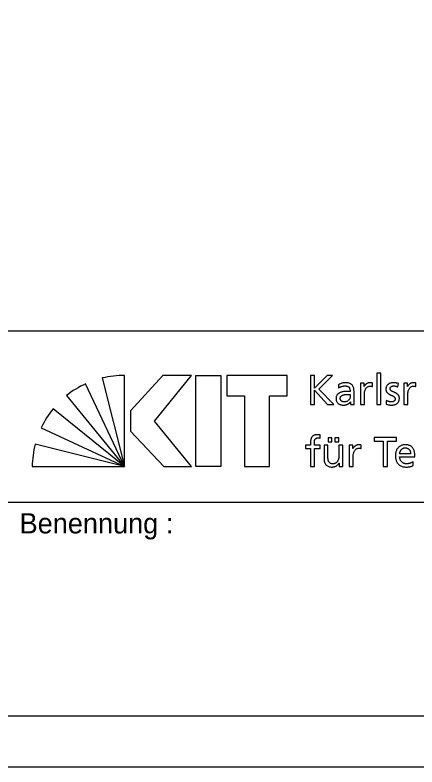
# Model space of a CAD drawing. Extents: x 0 to 42, y 0 to 59.4.
# Drawn here: x 24.33 to 32.27, y 0 to 14.85 of the extents above; entities that cross this region are included whole.
import ezdxf

# ---------------------------------------------------------------- set-up
doc = ezdxf.new("R2010")
doc.units = 0
doc.layers.add('90_Plankopf', color=7, linetype='Continuous')

msp = doc.modelspace()

# ---------------------------------------------------------------- linework, layer by layer
at = {"layer": '90_Plankopf'}
for p, q in [((5, 8.614), (41, 8.614)), ((26.496, 5.933), (26.496, 7.733)), ((30.162, 7.733), (30.162, 7.157)), ((26.055, 7.683), (26.496, 5.933)), ((31.385, 7.513), (31.385, 7.582)), ((32.242, 7.513), (32.242, 7.582)), ((26.496, 5.933), (25.727, 7.566)), ((30.716, 7.548), (30.72, 7.482)), ((31.891, 7.504), (31.898, 7.572)), ((25.349, 7.333), (26.496, 5.933)), ((30.946, 7.358), (30.946, 7.321)), ((31.024, 7.24), (31.024, 7.414)), ((30.162, 7.157), (30.244, 7.157)), ((30.501, 7.157), (30.622, 7.157)), ((31.659, 7.24), (31.655, 7.17)), ((26.496, 5.933), (25.087, 7.073)), ((24.848, 6.699), (26.496, 5.933)), ((30.355, 6.495), (30.358, 6.557)), ((26.496, 5.933), (24.732, 6.374)), ((31.165, 6.289), (31.165, 6.358)), ((32.141, 6.184), (31.923, 6.184)), ((31.923, 6.126), (32.224, 6.126)), ((32.192, 5.951), (32.192, 6.028)), ((24.673, 5.933), (26.496, 5.933)), ((21.73, 5.23), (41, 5.23))]:
    msp.add_line(p, q, dxfattribs=at)
for points in [[(0, 0), (42, 0), (42, 59.4), (0, 59.4)], [(5, 58.4), (41, 58.4), (41, 1), (5, 1)], [(27.813, 7.733), (27.247, 7.733), (26.615, 7.036), (26.615, 6.634), (27.268, 5.933), (27.817, 5.933), (27.084, 6.829)], [(28.394, 7.733), (28.394, 5.933), (27.9, 5.933), (27.9, 7.733)], [(28.512, 7.733), (28.512, 7.328), (28.86, 7.328), (28.86, 5.933), (29.354, 5.933), (29.354, 7.328), (29.702, 7.328), (29.702, 7.733)]]:
    msp.add_lwpolyline(points, close=True, dxfattribs=at)
for points in [[(30.622, 7.157), (30.329, 7.461), (30.6, 7.733), (30.49, 7.733), (30.244, 7.48), (30.244, 7.733), (30.162, 7.733)], [(31.476, 7.157), (31.554, 7.157), (31.554, 7.776), (31.476, 7.776), (31.476, 7.157)], [(31.224, 7.513), (31.223, 7.513), (31.223, 7.578), (31.15, 7.578), (31.15, 7.157), (31.228, 7.157), (31.228, 7.349)], [(32.081, 7.513), (32.08, 7.513), (32.08, 7.578), (32.007, 7.578), (32.007, 7.157), (32.085, 7.157), (32.085, 7.349)], [(30.244, 7.157), (30.244, 7.439), (30.501, 7.157)], [(30.953, 7.212), (30.954, 7.212), (30.954, 7.157), (31.027, 7.157)], [(30.165, 6.393), (30.165, 6.354), (30.066, 6.354), (30.066, 6.292), (30.165, 6.292), (30.165, 5.933), (30.242, 5.933), (30.242, 6.292), (30.354, 6.292), (30.354, 6.354), (30.242, 6.354), (30.242, 6.4)], [(30.511, 6.501), (30.511, 6.419), (30.588, 6.419), (30.588, 6.501), (30.511, 6.501)], [(30.646, 6.501), (30.646, 6.419), (30.724, 6.419), (30.724, 6.501), (30.646, 6.501)], [(31.598, 5.933), (31.681, 5.933), (31.681, 6.437), (31.86, 6.437), (31.86, 6.509), (31.419, 6.509), (31.419, 6.437), (31.598, 6.437), (31.598, 5.933)], [(30.508, 6.136), (30.508, 6.354), (30.431, 6.354), (30.431, 6.104)], [(30.803, 5.933), (30.803, 6.354), (30.725, 6.354), (30.725, 6.159)], [(31.004, 6.289), (31.003, 6.289), (31.003, 6.354), (30.93, 6.354), (30.93, 5.933), (31.008, 5.933), (31.008, 6.125)], [(30.726, 6), (30.728, 6), (30.728, 5.933), (30.803, 5.933)]]:
    msp.add_lwpolyline(points, dxfattribs=at)
for centre, start, end in [((26.49, 5.827), 89.8053, 103.1895), ((26.532, 5.84), 115.0126, 128.3968), ((26.563, 5.869), 140.7898, 154.174), ((26.578, 5.904), 165.7222, 179.1064)]:
    msp.add_arc(centre, 1.906, start, end, dxfattribs=at)
for points in [[(31.024, 7.414), (31.024, 7.452), (31.018, 7.484), (31.007, 7.51), (30.995, 7.536), (30.977, 7.555), (30.952, 7.568), (30.927, 7.581), (30.894, 7.588), (30.854, 7.588), (30.828, 7.588), (30.803, 7.584), (30.78, 7.577), (30.756, 7.57), (30.735, 7.56), (30.716, 7.548)], [(31.385, 7.582), (31.38, 7.583), (31.375, 7.584), (31.37, 7.585), (31.365, 7.586), (31.36, 7.587), (31.354, 7.587), (31.348, 7.588), (31.342, 7.588), (31.334, 7.588), (31.319, 7.588), (31.305, 7.585), (31.29, 7.578), (31.276, 7.572), (31.264, 7.563), (31.252, 7.552), (31.241, 7.541), (31.231, 7.528), (31.224, 7.513)], [(31.898, 7.572), (31.883, 7.576), (31.867, 7.58), (31.852, 7.583), (31.836, 7.586), (31.819, 7.588), (31.801, 7.588), (31.781, 7.588), (31.761, 7.585), (31.743, 7.58), (31.725, 7.575), (31.709, 7.567), (31.696, 7.556), (31.682, 7.545), (31.672, 7.532), (31.664, 7.516), (31.657, 7.499), (31.653, 7.48), (31.653, 7.458), (31.653, 7.442), (31.656, 7.427), (31.663, 7.415), (31.669, 7.403), (31.678, 7.392), (31.689, 7.383), (31.7, 7.374), (31.712, 7.366), (31.725, 7.359), (31.738, 7.352), (31.751, 7.345), (31.763, 7.339), (31.776, 7.333), (31.788, 7.327), (31.799, 7.32), (31.81, 7.314), (31.819, 7.307), (31.825, 7.299), (31.832, 7.291), (31.835, 7.281), (31.835, 7.27), (31.835, 7.259), (31.833, 7.249), (31.828, 7.242), (31.823, 7.234), (31.817, 7.228), (31.809, 7.223), (31.801, 7.218), (31.793, 7.215), (31.783, 7.213), (31.774, 7.211), (31.765, 7.21), (31.756, 7.21), (31.748, 7.21), (31.739, 7.211), (31.728, 7.213), (31.717, 7.215), (31.705, 7.219), (31.693, 7.223), (31.681, 7.228), (31.67, 7.233), (31.659, 7.24)], [(32.242, 7.582), (32.237, 7.583), (32.232, 7.584), (32.227, 7.585), (32.222, 7.586), (32.217, 7.587), (32.211, 7.587), (32.205, 7.588), (32.199, 7.588), (32.191, 7.588), (32.176, 7.588), (32.162, 7.585), (32.147, 7.578), (32.133, 7.572), (32.121, 7.563), (32.109, 7.552), (32.098, 7.541), (32.088, 7.528), (32.081, 7.513)], [(30.72, 7.482), (30.731, 7.491), (30.743, 7.499), (30.756, 7.505), (30.769, 7.512), (30.783, 7.517), (30.798, 7.52), (30.813, 7.524), (30.827, 7.525), (30.842, 7.525), (30.868, 7.525), (30.888, 7.521), (30.904, 7.513), (30.919, 7.505), (30.93, 7.493), (30.936, 7.476), (30.943, 7.46), (30.946, 7.44), (30.946, 7.415)], [(31.228, 7.349), (31.228, 7.384), (31.233, 7.415), (31.242, 7.44), (31.251, 7.466), (31.265, 7.486), (31.282, 7.499), (31.299, 7.513), (31.319, 7.52), (31.342, 7.52), (31.349, 7.52), (31.356, 7.52), (31.364, 7.519), (31.371, 7.518), (31.378, 7.516), (31.385, 7.513)], [(31.655, 7.17), (31.673, 7.161), (31.692, 7.155), (31.712, 7.152), (31.731, 7.148), (31.751, 7.147), (31.771, 7.147), (31.79, 7.147), (31.808, 7.15), (31.825, 7.155), (31.843, 7.16), (31.859, 7.168), (31.873, 7.179), (31.886, 7.19), (31.897, 7.204), (31.905, 7.22), (31.914, 7.237), (31.918, 7.256), (31.918, 7.278), (31.918, 7.298), (31.914, 7.314), (31.908, 7.327), (31.901, 7.34), (31.892, 7.352), (31.882, 7.361), (31.871, 7.37), (31.859, 7.378), (31.846, 7.385), (31.833, 7.392), (31.82, 7.398), (31.807, 7.403), (31.794, 7.409), (31.782, 7.415), (31.772, 7.421), (31.761, 7.428), (31.752, 7.435), (31.745, 7.443), (31.739, 7.452), (31.736, 7.462), (31.735, 7.474), (31.736, 7.486), (31.739, 7.495), (31.746, 7.503), (31.753, 7.51), (31.762, 7.516), (31.773, 7.52), (31.784, 7.524), (31.796, 7.525), (31.81, 7.525), (31.814, 7.525), (31.82, 7.525), (31.828, 7.524), (31.835, 7.522), (31.843, 7.521), (31.851, 7.519), (31.859, 7.517), (31.867, 7.514), (31.874, 7.512), (31.881, 7.509), (31.887, 7.507), (31.891, 7.504)], [(32.085, 7.349), (32.085, 7.384), (32.09, 7.415), (32.099, 7.44), (32.108, 7.466), (32.122, 7.486), (32.139, 7.499), (32.156, 7.513), (32.176, 7.52), (32.199, 7.52), (32.206, 7.52), (32.213, 7.52), (32.221, 7.519), (32.228, 7.518), (32.235, 7.516), (32.242, 7.513)], [(30.946, 7.415), (30.936, 7.416), (30.927, 7.416), (30.918, 7.417), (30.909, 7.417), (30.9, 7.417), (30.892, 7.417), (30.883, 7.417), (30.874, 7.417), (30.864, 7.417), (30.847, 7.417), (30.83, 7.416), (30.813, 7.413), (30.795, 7.41), (30.777, 7.405), (30.76, 7.399), (30.743, 7.392), (30.728, 7.384), (30.714, 7.373), (30.7, 7.362), (30.689, 7.349), (30.681, 7.334), (30.672, 7.318), (30.668, 7.3), (30.668, 7.278), (30.668, 7.248), (30.675, 7.223), (30.688, 7.204), (30.701, 7.184), (30.719, 7.17), (30.742, 7.161), (30.765, 7.152), (30.792, 7.147), (30.822, 7.147), (30.84, 7.147), (30.856, 7.15), (30.87, 7.154), (30.884, 7.158), (30.897, 7.163), (30.907, 7.17), (30.918, 7.176), (30.927, 7.183), (30.935, 7.191), (30.942, 7.198), (30.948, 7.205), (30.953, 7.212)], [(30.946, 7.321), (30.946, 7.3), (30.942, 7.281), (30.933, 7.264), (30.924, 7.247), (30.911, 7.234), (30.893, 7.225), (30.876, 7.215), (30.854, 7.21), (30.829, 7.21), (30.82, 7.21), (30.811, 7.212), (30.802, 7.214), (30.793, 7.217), (30.784, 7.222), (30.776, 7.227), (30.769, 7.233), (30.762, 7.241), (30.758, 7.249), (30.753, 7.257), (30.751, 7.267), (30.75, 7.278), (30.751, 7.293), (30.754, 7.306), (30.762, 7.315), (30.769, 7.325), (30.778, 7.333), (30.79, 7.339), (30.801, 7.345), (30.814, 7.349), (30.827, 7.352), (30.84, 7.355), (30.853, 7.357), (30.865, 7.358), (30.877, 7.359), (30.888, 7.359), (30.897, 7.359), (30.905, 7.359), (30.913, 7.359), (30.921, 7.359), (30.93, 7.358), (30.938, 7.358), (30.946, 7.358)], [(31.027, 7.157), (31.026, 7.161), (31.026, 7.167), (31.025, 7.173), (31.025, 7.18), (31.024, 7.189), (31.024, 7.2), (31.024, 7.211), (31.024, 7.224), (31.024, 7.24)], [(30.358, 6.557), (30.35, 6.558), (30.342, 6.56), (30.334, 6.561), (30.325, 6.562), (30.316, 6.562), (30.306, 6.562), (30.278, 6.562), (30.254, 6.558), (30.236, 6.55), (30.217, 6.542), (30.203, 6.531), (30.192, 6.516), (30.182, 6.501), (30.175, 6.483), (30.171, 6.463), (30.167, 6.442), (30.165, 6.419), (30.165, 6.393)], [(30.242, 6.4), (30.242, 6.414), (30.243, 6.427), (30.245, 6.439), (30.246, 6.451), (30.25, 6.462), (30.255, 6.471), (30.26, 6.48), (30.268, 6.487), (30.278, 6.492), (30.288, 6.497), (30.301, 6.499), (30.318, 6.499), (30.324, 6.499), (30.331, 6.499), (30.338, 6.498), (30.344, 6.497), (30.35, 6.496), (30.355, 6.495)], [(31.165, 6.358), (31.16, 6.359), (31.155, 6.36), (31.15, 6.361), (31.145, 6.362), (31.14, 6.363), (31.134, 6.363), (31.128, 6.364), (31.122, 6.364), (31.114, 6.364), (31.099, 6.364), (31.085, 6.361), (31.07, 6.354), (31.056, 6.348), (31.044, 6.339), (31.032, 6.328), (31.021, 6.317), (31.011, 6.304), (31.004, 6.289)], [(31.008, 6.125), (31.008, 6.16), (31.013, 6.191), (31.022, 6.216), (31.032, 6.242), (31.045, 6.262), (31.062, 6.275), (31.079, 6.289), (31.099, 6.296), (31.122, 6.296), (31.129, 6.297), (31.136, 6.296), (31.144, 6.295), (31.151, 6.294), (31.158, 6.292), (31.165, 6.289)], [(32.224, 6.126), (32.224, 6.16), (32.221, 6.192), (32.214, 6.221), (32.208, 6.25), (32.198, 6.275), (32.184, 6.296), (32.169, 6.317), (32.15, 6.334), (32.126, 6.346), (32.102, 6.358), (32.073, 6.364), (32.038, 6.364), (32.008, 6.364), (31.981, 6.359), (31.957, 6.348), (31.933, 6.338), (31.912, 6.323), (31.895, 6.304), (31.877, 6.285), (31.864, 6.263), (31.855, 6.237), (31.846, 6.211), (31.841, 6.183), (31.841, 6.151), (31.841, 6.117), (31.845, 6.086), (31.854, 6.058), (31.862, 6.03), (31.876, 6.006), (31.894, 5.986), (31.912, 5.966), (31.934, 5.95), (31.962, 5.94), (31.989, 5.929), (32.021, 5.924), (32.059, 5.923), (32.082, 5.924), (32.101, 5.925), (32.117, 5.928), (32.133, 5.931), (32.147, 5.935), (32.159, 5.939), (32.171, 5.943), (32.182, 5.947), (32.192, 5.951)], [(31.923, 6.184), (31.925, 6.198), (31.928, 6.212), (31.933, 6.225), (31.938, 6.239), (31.944, 6.252), (31.954, 6.263), (31.962, 6.275), (31.974, 6.284), (31.987, 6.291), (32.001, 6.298), (32.017, 6.301), (32.036, 6.301), (32.053, 6.301), (32.068, 6.298), (32.081, 6.292), (32.094, 6.286), (32.105, 6.278), (32.114, 6.267), (32.123, 6.256), (32.13, 6.244), (32.134, 6.23), (32.139, 6.216), (32.141, 6.2), (32.141, 6.184)], [(30.431, 6.104), (30.431, 6.066), (30.436, 6.034), (30.447, 6.007), (30.459, 5.98), (30.476, 5.959), (30.499, 5.945), (30.522, 5.931), (30.552, 5.924), (30.588, 5.923), (30.608, 5.924), (30.627, 5.927), (30.645, 5.933), (30.663, 5.939), (30.679, 5.948), (30.693, 5.959), (30.707, 5.97), (30.718, 5.984), (30.726, 6)], [(30.725, 6.159), (30.725, 6.134), (30.723, 6.11), (30.718, 6.089), (30.713, 6.068), (30.705, 6.05), (30.695, 6.034), (30.684, 6.019), (30.671, 6.007), (30.655, 5.999), (30.639, 5.99), (30.619, 5.986), (30.597, 5.986), (30.575, 5.987), (30.557, 5.994), (30.544, 6.005), (30.531, 6.016), (30.522, 6.033), (30.516, 6.055), (30.511, 6.076), (30.508, 6.104), (30.508, 6.136)], [(32.192, 6.028), (32.187, 6.024), (32.18, 6.02), (32.17, 6.015), (32.161, 6.01), (32.151, 6.006), (32.139, 6.001), (32.127, 5.997), (32.114, 5.993), (32.101, 5.99), (32.088, 5.988), (32.075, 5.986), (32.062, 5.986), (32.043, 5.986), (32.026, 5.99), (32.009, 5.996), (31.993, 6.003), (31.978, 6.013), (31.965, 6.025), (31.952, 6.037), (31.942, 6.052), (31.935, 6.069), (31.927, 6.087), (31.923, 6.106), (31.923, 6.126)]]:
    msp.add_open_spline(points, degree=3, dxfattribs=at)

# ---------------------------------------------------------------- texts
msp.add_text('Benennung :', height=0.4, dxfattribs=at).set_placement((24.423, 4.612))

doc.saveas('drawing.dxf')
